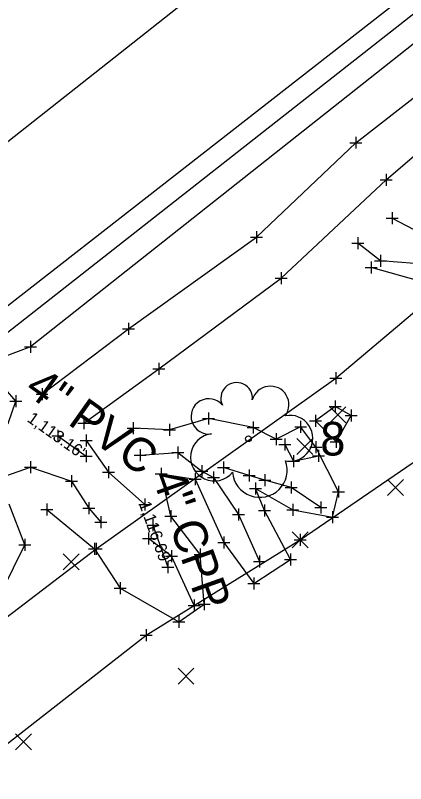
# Model space of a CAD drawing. Extents: x 2184635 to 2185378, y 369880 to 370486.
# Drawn here: x 2184875.3 to 2184907.9, y 370026.6 to 370090.6 of the extents above; entities that cross this region are included whole.
import ezdxf

# ---------------------------------------------------------------- set-up
doc = ezdxf.new("R2010")
doc.units = 0
for name, color, linetype in [('_CIVIL_CONSTRUCTION', 7, 'Continuous'), ('DR_X_Ditch', 7, 'Continuous'), ('DR_X_Storm_Sewer', 7, 'Continuous'), ('DR_X_Text', 7, 'Continuous'), ('GE_X_Alignment', 7, 'Continuous'), ('GE_X_Alignment_100_Distances', 7, 'Continuous'), ('PM_X_CL_Pass_Proh_Lt', 7, 'Continuous'), ('PM_X_CL_Pass_Proh_Rt', 7, 'Continuous'), ('PV_X_COP', 7, 'Continuous'), ('PV_X_EOP', 7, 'Continuous'), ('PV_X_Shoulder', 7, 'Continuous'), ('RD_X_Fence', 7, 'Continuous'), ('RW_X_CL', 7, 'Continuous'), ('RW_X_CL_100_Bearings', 7, 'Continuous'), ('SC_Scratch1', 7, 'Continuous'), ('SV_X_Break_Lines', 7, 'Continuous'), ('UT_X_Gas', 7, 'Continuous'), ('VG_X_Text', 7, 'Continuous')]:
    doc.layers.add(name, color=color, linetype=linetype)

msp = doc.modelspace()

# ---------------------------------------------------------------- linework, layer by layer
at = {"layer": '_CIVIL_CONSTRUCTION'}
for p, q in [((2184901.56, 370056.663), (2184902.894, 370057.998)), ((2184901.56, 370057.998), (2184902.894, 370056.663)), ((2184898.808, 370054.02), (2184900.141, 370055.355)), ((2184898.808, 370055.355), (2184900.141, 370054.02)), ((2184906.361, 370050.578), (2184907.694, 370051.913)), ((2184906.361, 370051.913), (2184907.694, 370050.578)), ((2184898.406, 370046.217), (2184899.739, 370047.552)), ((2184898.406, 370047.552), (2184899.739, 370046.217)), ((2184879.313, 370044.406), (2184880.646, 370045.741)), ((2184879.313, 370045.741), (2184880.646, 370044.406)), ((2184888.893, 370034.857), (2184890.226, 370036.192)), ((2184888.893, 370036.192), (2184890.226, 370034.857)), ((2184875.333, 370029.397), (2184876.666, 370030.732)), ((2184875.333, 370030.732), (2184876.666, 370029.397))]:
    msp.add_line(p, q, dxfattribs=at)
at = {"layer": 'DR_X_Ditch'}
for points in [[(2184849.239, 370033.73), (2184855.751, 370040.4), (2184859.676, 370043.207), (2184861.454, 370044.268), (2184864.118, 370046.317), (2184865.643, 370047.216), (2184866.527, 370048.333), (2184869.021, 370050.508), (2184872.418, 370054.082), (2184874.729, 370056.587), (2184875.359, 370058.466), (2184874.504, 370059.447)], [(2184890.236, 370041.407), (2184888.359, 370045.528), (2184886.422, 370046.995)]]:
    msp.add_lwpolyline(points, dxfattribs=at)
at = {"layer": 'DR_X_Storm_Sewer'}
for p, q in [((2184878.862, 370055.567), (2184881.239, 370053.88)), ((2184886.793, 370048.109), (2184888.035, 370044.625))]:
    msp.add_line(p, q, dxfattribs=at)
at = {"layer": 'GE_X_Alignment'}
msp.add_circle((2184894.765, 370055.326), 0.24, dxfattribs=at)
for centre, radius, start, end in [((2184893.781, 370058.693), 1.317, 354.0047, 205.97412), ((2184896.591, 370058.155), 1.553, 323.82996, 165.0376), ((2184891.455, 370057.19), 1.471, 39.06254, 279.54124), ((2184898.225, 370055.362), 1.915, 259.14531, 101.45961), ((2184891.911, 370053.777), 1.974, 96.17219, 320.57371), ((2184895.711, 370052.721), 2.284, 184.94757, 19.45715)]:
    msp.add_arc(centre, radius, start, end, dxfattribs=at)
at = {"layer": 'GE_X_Alignment_100_Distances'}
msp.add_lwpolyline([(2185264.317, 370371.308), (2185225.669, 370339.838), (2185186.917, 370307.744), (2185148.745, 370277.089), (2185109.073, 370245.724), (2185070.468, 370214.753), (2185031.044, 370183.419), (2184991.951, 370153.137), (2184952.243, 370122.384), (2184912.885, 370091.687), (2184876.597, 370062.99), (2184874.528, 370062.204), (2184872.479, 370060.466), (2184871.454, 370058.823), (2184869.46, 370057.791), (2184834.83, 370028.947), (2184796.151, 369998.173), (2184773.728, 369979.618), (2184757.686, 369965.832), (2184717.275, 369935.855), (2184678.357, 369904.181)], dxfattribs=at)
at = {"layer": 'PM_X_CL_Pass_Proh_Lt'}
msp.add_lwpolyline([(2185262.142, 370374.202), (2185223.699, 370342.03), (2185185.178, 370310.659), (2185146.677, 370279.544), (2185107.738, 370248.35), (2185068.5, 370216.963), (2185029.051, 370186.04), (2184989.472, 370156.275), (2184949.89, 370125.369), (2184910.765, 370094.563), (2184870.979, 370063.529), (2184832.077, 370032.401), (2184793.204, 370001.486), (2184754.34, 369970.024), (2184715.121, 369938.505), (2184676.144, 369907.221)], dxfattribs=at)
at = {"layer": 'PM_X_CL_Pass_Proh_Rt'}
msp.add_lwpolyline([(2184772.075, 369998.33), (2184786.357, 370009.443), (2184824.962, 370040.257), (2184864.241, 370071.885), (2184905.968, 370104.805), (2184943.399, 370133.995), (2184983.483, 370165.213), (2185020.257, 370194.467), (2185061.224, 370226.635), (2185099.743, 370257.779), (2185139.182, 370289.511), (2185177.352, 370320.307), (2185216.054, 370351.804), (2185254.728, 370383.452)], dxfattribs=at)
at = {"layer": 'PV_X_COP'}
msp.add_lwpolyline([(2184667.936, 369914.544), (2184708.437, 369946.755), (2184746.444, 369977.522), (2184786.357, 370009.443), (2184824.962, 370040.257), (2184864.241, 370071.885), (2184905.968, 370104.805), (2184943.399, 370133.995), (2184983.483, 370165.213), (2185020.257, 370194.467), (2185061.224, 370226.635), (2185099.743, 370257.779), (2185139.182, 370289.511), (2185177.352, 370320.307), (2185216.054, 370351.804), (2185254.679, 370383.196)], dxfattribs=at)
at = {"layer": 'PV_X_EOP'}
msp.add_lwpolyline([(2185262.152, 370374.256), (2185223.699, 370342.03), (2185185.178, 370310.659), (2185146.677, 370279.544), (2185107.738, 370248.35), (2185068.5, 370216.963), (2185029.051, 370186.04), (2184989.472, 370156.275), (2184949.89, 370125.369), (2184910.765, 370094.563), (2184870.979, 370063.529), (2184832.077, 370032.401), (2184793.204, 370001.486), (2184754.34, 369970.024), (2184715.121, 369938.505), (2184676.223, 369907.131)], dxfattribs=at)
at = {"layer": 'PV_X_Shoulder'}
msp.add_lwpolyline([(2185263.127, 370373.08), (2185224.626, 370341.08), (2185185.979, 370309.587), (2185147.251, 370278.484), (2185108.316, 370247.412), (2185069.303, 370216.141), (2185029.865, 370185.151), (2184990.36, 370154.899), (2184951.083, 370123.826), (2184911.784, 370093.315), (2184872.077, 370062.156), (2184833.336, 370030.958), (2184794.18, 369999.967), (2184755.603, 369968.652), (2184716.02, 369937.324), (2184677.487, 369905.633)], dxfattribs=at)
at = {"layer": 'RD_X_Fence'}
msp.add_lwpolyline([(2184782.754, 369936.252), (2184778.788, 369962.291), (2184805.018, 369984.824), (2184835.149, 370010.167), (2184846.096, 370019.315), (2184858.499, 370028.169), (2184882.065, 370046.135), (2184902.067, 370060.364), (2184933.298, 370086.709), (2184952.934, 370104.808), (2184969.351, 370118.703)], dxfattribs=at)
at = {"layer": 'RW_X_CL'}
for p, q in [((2184903.212, 370080.01), (2184904.212, 370080.01)), ((2184903.712, 370080.51), (2184903.712, 370079.51)), ((2184903.712, 370080.01), (2184903.712, 370080.01)), ((2184906.263, 370077.399), (2184906.263, 370076.399)), ((2184905.763, 370076.899), (2184906.763, 370076.899)), ((2184906.263, 370076.899), (2184906.263, 370076.899)), ((2184906.753, 370074.214), (2184906.753, 370073.214)), ((2184906.253, 370073.714), (2184907.253, 370073.714)), ((2184906.753, 370073.714), (2184906.753, 370073.714)), ((2184895.426, 370072.636), (2184895.426, 370071.636)), ((2184894.926, 370072.136), (2184895.926, 370072.136)), ((2184895.426, 370072.136), (2184895.426, 370072.136)), ((2184903.401, 370071.643), (2184904.401, 370071.643)), ((2184903.901, 370072.143), (2184903.901, 370071.143)), ((2184903.901, 370071.643), (2184903.901, 370071.643)), ((2184905.778, 370070.658), (2184905.778, 370069.658)), ((2184904.99, 370070.103), (2184904.99, 370069.103)), ((2184905.278, 370070.158), (2184906.278, 370070.158)), ((2184905.778, 370070.158), (2184905.778, 370070.158)), ((2184897.496, 370069.219), (2184897.496, 370068.219)), ((2184904.49, 370069.603), (2184905.49, 370069.603)), ((2184904.99, 370069.603), (2184904.99, 370069.603)), ((2184896.996, 370068.719), (2184897.996, 370068.719)), ((2184897.496, 370068.719), (2184897.496, 370068.719)), ((2184884.763, 370064.982), (2184884.763, 370063.982)), ((2184884.263, 370064.482), (2184885.263, 370064.482)), ((2184884.763, 370064.482), (2184884.763, 370064.482)), ((2184876.597, 370063.49), (2184876.597, 370062.49)), ((2184876.097, 370062.99), (2184877.097, 370062.99)), ((2184876.597, 370062.99), (2184876.597, 370062.99)), ((2184887.302, 370061.66), (2184887.302, 370060.66)), ((2184886.802, 370061.16), (2184887.802, 370061.16)), ((2184887.302, 370061.16), (2184887.302, 370061.16)), ((2184902.067, 370060.864), (2184902.067, 370059.864)), ((2184901.567, 370060.364), (2184902.567, 370060.364)), ((2184902.067, 370060.364), (2184902.067, 370060.364)), ((2184877.551, 370059.528), (2184877.551, 370058.528)), ((2184875.359, 370058.966), (2184875.359, 370057.966)), ((2184877.051, 370059.028), (2184878.051, 370059.028)), ((2184877.551, 370059.028), (2184877.551, 370059.028)), ((2184874.859, 370058.466), (2184875.859, 370058.466)), ((2184875.359, 370058.466), (2184875.359, 370058.466)), ((2184901.991, 370058.515), (2184901.991, 370057.515)), ((2184891.448, 370057.517), (2184891.448, 370056.517)), ((2184901.491, 370058.015), (2184902.491, 370058.015)), ((2184901.991, 370058.015), (2184901.991, 370058.015)), ((2184903.328, 370057.771), (2184903.328, 370056.771)), ((2184881.037, 370057.135), (2184881.037, 370056.135)), ((2184890.948, 370057.017), (2184891.948, 370057.017)), ((2184891.448, 370057.017), (2184891.448, 370057.017)), ((2184899.122, 370056.813), (2184899.122, 370055.813)), ((2184899.852, 370056.82), (2184900.852, 370056.82)), ((2184900.352, 370057.32), (2184900.352, 370056.32)), ((2184900.352, 370056.82), (2184900.352, 370056.82)), ((2184902.828, 370057.271), (2184903.828, 370057.271)), ((2184903.328, 370057.271), (2184903.328, 370057.271)), ((2184880.537, 370056.635), (2184881.537, 370056.635)), ((2184881.037, 370056.635), (2184881.037, 370056.635)), ((2184884.658, 370056.207), (2184885.658, 370056.207)), ((2184885.158, 370056.707), (2184885.158, 370055.707)), ((2184885.158, 370056.207), (2184885.158, 370056.207)), ((2184888.195, 370056.566), (2184888.195, 370055.566)), ((2184894.661, 370056.263), (2184895.661, 370056.263)), ((2184895.161, 370056.763), (2184895.161, 370055.763)), ((2184895.161, 370056.263), (2184895.161, 370056.263)), ((2184898.622, 370056.313), (2184899.622, 370056.313)), ((2184899.122, 370056.313), (2184899.122, 370056.313)), ((2184881.222, 370055.671), (2184881.222, 370054.671)), ((2184887.695, 370056.066), (2184888.695, 370056.066)), ((2184888.195, 370056.066), (2184888.195, 370056.066)), ((2184897.083, 370055.787), (2184897.083, 370054.787)), ((2184902.096, 370055.562), (2184902.096, 370054.562)), ((2184880.722, 370055.171), (2184881.722, 370055.171)), ((2184881.222, 370055.171), (2184881.222, 370055.171)), ((2184896.583, 370055.287), (2184897.583, 370055.287)), ((2184897.083, 370055.287), (2184897.083, 370055.287)), ((2184897.811, 370055.357), (2184897.811, 370054.357)), ((2184900.379, 370055.112), (2184900.379, 370054.112)), ((2184901.596, 370055.062), (2184902.596, 370055.062)), ((2184902.096, 370055.062), (2184902.096, 370055.062)), ((2184885.732, 370054.452), (2184885.732, 370053.452)), ((2184888.879, 370054.671), (2184888.879, 370053.671)), ((2184897.311, 370054.857), (2184898.311, 370054.857)), ((2184897.811, 370054.857), (2184897.811, 370054.857)), ((2184899.879, 370054.612), (2184900.879, 370054.612)), ((2184900.379, 370054.612), (2184900.379, 370054.612)), ((2184900.6, 370054.395), (2184900.6, 370053.395)), ((2184885.232, 370053.952), (2184886.232, 370053.952)), ((2184885.732, 370053.952), (2184885.732, 370053.952)), ((2184888.379, 370054.171), (2184889.379, 370054.171)), ((2184888.879, 370054.171), (2184888.879, 370054.171)), ((2184898.531, 370053.951), (2184898.531, 370052.951)), ((2184900.1, 370053.895), (2184901.1, 370053.895)), ((2184900.6, 370053.895), (2184900.6, 370053.895)), ((2184876.592, 370053.442), (2184876.592, 370052.442)), ((2184883.103, 370053.03), (2184883.103, 370052.03)), ((2184890.885, 370053.13), (2184890.885, 370052.13)), ((2184892.697, 370053.424), (2184892.697, 370052.424)), ((2184898.031, 370053.451), (2184899.031, 370053.451)), ((2184898.531, 370053.451), (2184898.531, 370053.451)), ((2184876.092, 370052.942), (2184877.092, 370052.942)), ((2184876.592, 370052.942), (2184876.592, 370052.942)), ((2184882.603, 370052.53), (2184883.603, 370052.53)), ((2184883.103, 370052.53), (2184883.103, 370052.53)), ((2184887, 370052.396), (2184888, 370052.396)), ((2184887.5, 370052.896), (2184887.5, 370051.896)), ((2184887.5, 370052.396), (2184887.5, 370052.396)), ((2184890.317, 370052.455), (2184890.317, 370051.455)), ((2184890.385, 370052.63), (2184891.385, 370052.63)), ((2184890.885, 370052.63), (2184890.885, 370052.63)), ((2184891.858, 370052.591), (2184891.858, 370051.591)), ((2184892.197, 370052.924), (2184893.197, 370052.924)), ((2184892.697, 370052.924), (2184892.697, 370052.924)), ((2184894.819, 370052.769), (2184894.819, 370051.769)), ((2184896.144, 370052.366), (2184896.144, 370051.366)), ((2184879.504, 370051.775), (2184880.504, 370051.775)), ((2184880.004, 370052.275), (2184880.004, 370051.275)), ((2184880.004, 370051.775), (2184880.004, 370051.775)), ((2184889.817, 370051.955), (2184890.817, 370051.955)), ((2184890.317, 370051.955), (2184890.317, 370051.955)), ((2184891.358, 370052.091), (2184892.358, 370052.091)), ((2184891.858, 370052.091), (2184891.858, 370052.091)), ((2184894.319, 370052.269), (2184895.319, 370052.269)), ((2184894.819, 370052.269), (2184894.819, 370052.269)), ((2184895.644, 370051.866), (2184896.644, 370051.866)), ((2184896.144, 370051.866), (2184896.144, 370051.866)), ((2184898.329, 370051.75), (2184898.329, 370050.75)), ((2184894.858, 370051.163), (2184895.858, 370051.163)), ((2184895.358, 370051.663), (2184895.358, 370050.663)), ((2184895.358, 370051.163), (2184895.358, 370051.163)), ((2184897.829, 370051.25), (2184898.829, 370051.25)), ((2184898.329, 370051.25), (2184898.329, 370051.25)), ((2184902.275, 370051.411), (2184902.275, 370050.411)), ((2184901.775, 370050.911), (2184902.775, 370050.911)), ((2184902.275, 370050.911), (2184902.275, 370050.911)), ((2184877.947, 370049.934), (2184877.947, 370048.934)), ((2184881.445, 370050.04), (2184881.445, 370049.04)), ((2184885.628, 370049.843), (2184886.628, 370049.843)), ((2184886.128, 370050.343), (2184886.128, 370049.343)), ((2184886.128, 370049.843), (2184886.128, 370049.843)), ((2184896.095, 370049.85), (2184896.095, 370048.85)), ((2184898.455, 370049.9), (2184898.455, 370048.9)), ((2184900.806, 370050.097), (2184900.806, 370049.097)), ((2184877.447, 370049.434), (2184878.447, 370049.434)), ((2184877.947, 370049.434), (2184877.947, 370049.434)), ((2184880.945, 370049.54), (2184881.945, 370049.54)), ((2184881.445, 370049.54), (2184881.445, 370049.54)), ((2184888.3, 370049.374), (2184888.3, 370048.374)), ((2184893.93, 370049.505), (2184893.93, 370048.505)), ((2184895.595, 370049.35), (2184896.595, 370049.35)), ((2184896.095, 370049.35), (2184896.095, 370049.35)), ((2184897.955, 370049.4), (2184898.955, 370049.4)), ((2184898.455, 370049.4), (2184898.455, 370049.4)), ((2184900.306, 370049.597), (2184901.306, 370049.597)), ((2184900.806, 370049.597), (2184900.806, 370049.597)), ((2184901.767, 370049.278), (2184901.767, 370048.278)), ((2184882.459, 370048.857), (2184882.459, 370047.857)), ((2184887.8, 370048.874), (2184888.8, 370048.874)), ((2184888.3, 370048.874), (2184888.3, 370048.874)), ((2184893.43, 370049.005), (2184894.43, 370049.005)), ((2184893.93, 370049.005), (2184893.93, 370049.005)), ((2184901.267, 370048.778), (2184902.267, 370048.778)), ((2184901.767, 370048.778), (2184901.767, 370048.778)), ((2184881.959, 370048.357), (2184882.959, 370048.357)), ((2184882.459, 370048.357), (2184882.459, 370048.357)), ((2184886.422, 370047.495), (2184886.422, 370046.495)), ((2184899.072, 370047.385), (2184899.072, 370046.385)), ((2184876.119, 370046.988), (2184876.119, 370045.988)), ((2184881.942, 370046.652), (2184881.942, 370045.652)), ((2184882.065, 370046.635), (2184882.065, 370045.635)), ((2184885.922, 370046.995), (2184886.922, 370046.995)), ((2184886.422, 370046.995), (2184886.422, 370046.995)), ((2184892.204, 370046.685), (2184893.204, 370046.685)), ((2184892.704, 370047.185), (2184892.704, 370046.185)), ((2184892.704, 370046.685), (2184892.704, 370046.685)), ((2184898.572, 370046.885), (2184899.572, 370046.885)), ((2184899.072, 370046.885), (2184899.072, 370046.885)), ((2184875.619, 370046.488), (2184876.619, 370046.488)), ((2184876.119, 370046.488), (2184876.119, 370046.488)), ((2184881.442, 370046.152), (2184882.442, 370046.152)), ((2184881.565, 370046.135), (2184882.565, 370046.135)), ((2184881.942, 370046.152), (2184881.942, 370046.152)), ((2184882.065, 370046.135), (2184882.065, 370046.135)), ((2184888.359, 370046.028), (2184888.359, 370045.028)), ((2184890.747, 370046.165), (2184890.747, 370045.165)), ((2184887.859, 370045.528), (2184888.859, 370045.528)), ((2184888.359, 370045.528), (2184888.359, 370045.528)), ((2184890.247, 370045.665), (2184891.247, 370045.665)), ((2184890.747, 370045.665), (2184890.747, 370045.665)), ((2184895.699, 370045.579), (2184895.699, 370044.579)), ((2184898.273, 370045.746), (2184898.273, 370044.746)), ((2184895.199, 370045.079), (2184896.199, 370045.079)), ((2184895.699, 370045.079), (2184895.699, 370045.079)), ((2184897.773, 370045.246), (2184898.773, 370045.246)), ((2184898.273, 370045.246), (2184898.273, 370045.246)), ((2184895.213, 370043.757), (2184895.213, 370042.757)), ((2184883.578, 370042.858), (2184884.578, 370042.858)), ((2184884.078, 370043.358), (2184884.078, 370042.358)), ((2184884.078, 370042.858), (2184884.078, 370042.858)), ((2184894.713, 370043.257), (2184895.713, 370043.257)), ((2184895.213, 370043.257), (2184895.213, 370043.257)), ((2184890.236, 370041.907), (2184890.236, 370040.907)), ((2184890.567, 370041.523), (2184891.567, 370041.523)), ((2184891.067, 370042.023), (2184891.067, 370041.023)), ((2184891.067, 370041.523), (2184891.067, 370041.523)), ((2184889.736, 370041.407), (2184890.736, 370041.407)), ((2184890.236, 370041.407), (2184890.236, 370041.407)), ((2184888.962, 370040.563), (2184888.962, 370039.563)), ((2184888.462, 370040.063), (2184889.462, 370040.063)), ((2184888.962, 370040.063), (2184888.962, 370040.063)), ((2184885.731, 370038.937), (2184886.731, 370038.937)), ((2184886.231, 370039.437), (2184886.231, 370038.437)), ((2184886.231, 370038.937), (2184886.231, 370038.937))]:
    msp.add_line(p, q, dxfattribs=at)
at = {"layer": 'RW_X_CL_100_Bearings'}
for p, q in [((2184878.362, 370055.567), (2184879.362, 370055.567)), ((2184878.862, 370056.067), (2184878.862, 370055.067)), ((2184878.862, 370055.567), (2184878.862, 370055.567)), ((2184881.239, 370054.38), (2184881.239, 370053.38)), ((2184880.739, 370053.88), (2184881.739, 370053.88)), ((2184881.239, 370053.88), (2184881.239, 370053.88)), ((2184886.793, 370048.609), (2184886.793, 370047.609)), ((2184886.293, 370048.109), (2184887.293, 370048.109)), ((2184886.793, 370048.109), (2184886.793, 370048.109)), ((2184888.035, 370045.125), (2184888.035, 370044.125)), ((2184887.535, 370044.625), (2184888.535, 370044.625)), ((2184888.035, 370044.625), (2184888.035, 370044.625))]:
    msp.add_line(p, q, dxfattribs=at)
at = {"layer": 'SV_X_Break_Lines'}
for points in [[(2184877.551, 370059.028), (2184884.763, 370064.482), (2184895.426, 370072.136), (2184903.712, 370080.01), (2184915.313, 370089.034), (2184927.655, 370099.056), (2184938.515, 370107.685), (2184946.67, 370114.52), (2184954.238, 370120.081), (2184966.175, 370129.687), (2184977.964, 370136.606), (2184983.894, 370140.174), (2184990.927, 370144.207), (2185001.713, 370152.525), (2185005.564, 370154.266)], [(2184881.037, 370056.635), (2184887.302, 370061.16), (2184897.496, 370068.719), (2184906.263, 370076.899), (2184917.263, 370086.354), (2184930.975, 370096.702), (2184941.021, 370105.171), (2184949.47, 370110.555), (2184956.364, 370117.136), (2184969.257, 370127.938), (2184979.06, 370134.464), (2184985.468, 370138.655), (2184992.006, 370142.746), (2185002.661, 370150.56), (2185005.414, 370152.872)], [(2184906.753, 370073.714), (2184909.143, 370072.464), (2184913.589, 370070.961), (2184918.565, 370070.758), (2184922.337, 370068.184), (2184920.694, 370067.036), (2184916.066, 370067.304), (2184912.049, 370067.402), (2184909.046, 370068.475), (2184904.99, 370069.603)], [(2184922.31, 370067.421), (2184917.504, 370068.984), (2184913.249, 370069.457), (2184910.63, 370070.026), (2184910.039, 370069.833), (2184905.778, 370070.158), (2184903.901, 370071.643)], [(2184877.947, 370049.434), (2184881.942, 370046.152), (2184884.078, 370042.858), (2184888.962, 370040.063), (2184891.067, 370041.523), (2184890.747, 370045.665), (2184888.3, 370048.874), (2184887.5, 370052.396), (2184890.317, 370051.955), (2184892.704, 370046.685), (2184895.213, 370043.257), (2184898.273, 370045.246), (2184896.095, 370049.35), (2184895.358, 370051.163), (2184898.455, 370049.4), (2184901.767, 370048.778), (2184902.275, 370050.911), (2184900.379, 370054.612), (2184899.122, 370056.313), (2184897.083, 370055.287), (2184895.161, 370056.263), (2184891.448, 370057.017), (2184888.195, 370056.066), (2184885.158, 370056.207)], [(2184881.222, 370055.171), (2184883.103, 370052.53), (2184886.128, 370049.843)], [(2184897.811, 370054.857), (2184898.531, 370053.451), (2184900.6, 370053.895)], [(2184885.732, 370053.952), (2184888.879, 370054.171), (2184890.885, 370052.63), (2184891.858, 370052.091), (2184893.93, 370049.005), (2184895.699, 370045.079)], [(2184773.099, 369972.331), (2184782.4, 369979.42), (2184789.638, 369983.788), (2184799.975, 369993.188), (2184809.134, 369999.332), (2184821.188, 370007.547), (2184840.048, 370022.345), (2184850.57, 370031.252), (2184859.1, 370037.281), (2184862.334, 370042.107), (2184866.927, 370045.869), (2184870.157, 370048.473), (2184873.468, 370051.874), (2184876.592, 370052.942), (2184880.004, 370051.775), (2184881.445, 370049.54), (2184882.459, 370048.357)], [(2184900.806, 370049.597), (2184898.329, 370051.25), (2184896.144, 370051.866), (2184894.819, 370052.269), (2184892.697, 370052.924)], [(2184871.692, 370043.782), (2184870.452, 370039.558), (2184871.044, 370037.074), (2184869.637, 370034.98), (2184869.704, 370032.32), (2184872.117, 370034.028), (2184872.18, 370037.177), (2184873.282, 370040.777), (2184876.119, 370046.488), (2184874.826, 370049.868)]]:
    msp.add_lwpolyline(points, dxfattribs=at)
msp.add_lwpolyline([(2184902.096, 370055.062), (2184903.328, 370057.271), (2184901.991, 370058.015), (2184900.352, 370056.82)], close=True, dxfattribs=at)
at = {"layer": 'UT_X_Gas'}
msp.add_lwpolyline([(2184699.867, 369890.142), (2184718.364, 369905.922), (2184745.493, 369924.984), (2184756.714, 369934.518), (2184762.36, 369938.036), (2184795.231, 369963.996), (2184842.055, 370004.454), (2184886.231, 370038.937), (2184899.072, 370046.885), (2184918.449, 370060.147), (2184933.569, 370078.059), (2184948.534, 370093.678)], dxfattribs=at)

# ---------------------------------------------------------------- texts
at = {"layer": 'DR_X_Text'}
for s, rotation, p in [('4" PVC', 324.62844, (2184875.98, 370059.168)), ('4" CPP', 289.62975, (2184886.673, 370052.218))]:
    msp.add_text(s, height=2.8, rotation=rotation, dxfattribs=at).set_placement(p)
at = {"layer": 'SC_Scratch1'}
for s, rotation, p in [("1,113.16'", 324.62844, (2184876.235, 370056.819)), ("1,116.69'", 289.62975, (2184885.622, 370049.902))]:
    msp.add_text(s, height=1, rotation=rotation, dxfattribs=at).set_placement(p)
at = {"layer": 'VG_X_Text'}
msp.add_text('8', height=2.8, dxfattribs=at).set_placement((2184900.765, 370053.926))

doc.saveas('drawing.dxf')
